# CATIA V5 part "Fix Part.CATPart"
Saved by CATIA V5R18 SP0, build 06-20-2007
Part number: Part4
Bounding box of the stored display mesh (mm): x -100 to 100, y -30 to 50, z -10 to 111
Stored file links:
  D:\shriniwas\v5_r19\c16_CAT_v5r19\c16_Part\Rack Joint\Fix Part.CATPart
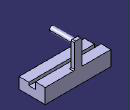
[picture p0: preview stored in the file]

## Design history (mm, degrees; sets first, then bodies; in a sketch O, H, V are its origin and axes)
Body1 (main body)
  Sketch1 on yz-plane, origin (0, 0, 0), H (0, 1, 0), V (0, 0, 1)
    line L1 (50, 35) -> (50, -10)
    line L2 (50, -10) -> (-30, -10)
    line L3 (0, 15) -> (20, 15)
    line L4 (20, 15) -> (20, 35)
    point P5 (0, 15)
    reference intersected line E1 through (0, 0) direction (-1, 0) from xy-plane
    reference intersected line E3 through (0, 0) direction (0, 1) from zx-plane
    line L5 (20, 35) -> (50, 35)
    reference intersected line E4 through (0, 0) direction (-1, 0) from xy-plane
    reference intersected line E6 through (0, 0) direction (0, 1) from zx-plane
    line L6 (0, 15) -> (0, 24)
    line L7 (0, 24) -> (-30, 24)
    line L8 (-30, 24) -> (-30, -10)
    distance H L2 = 10
    distance V L1 = 50
    distance E1 L3 = 15
    length L6 = 9
    length L4 = 20
    length L3 = 20
    length L2 = 80
    vertical: L1 V, L4 V, E3 V, E6 V, L6 V, L8 V
    horizontal: L2 H, L3 H, E1 H, L5 H, E4 H, L7 H
    perpendicularity: E1 L1
    coincidence: P5 V
  Pad1: profile Sketch1, direction (1, 0, 0), length 100, mirrored extent
  Sketch2 on face of Pad1 from Sketch1.L1, origin (0, 50, 0), H (-1, 0, 0), V (0, 0, 1)
    circle A1 centre (0, 100) radius 7.5
    point P1 (0, 100)
    radius A1 = 7.5
    distance H P1 = 100
    coincidence: P1 V
  Pad2: profile Sketch2, direction (0, -1, 0), up to face of Pad1 from Sketch1.L8
  Sketch3 on face of Pad1 from Sketch1.L1, origin (0, 50, 0), H (-1, 0, 0), V (0, 0, 1)
    line L1 (-11, 111) -> (11, 111)
    line L2 (11, 111) -> (11, -10)
    line L3 (11, -10) -> (-11, -10)
    line L4 (-11, -10) -> (-11, 111)
    length L3 = 22
    distance V L2 = 11
    distance L1 L3 = 121
    distance L3 H = 10
    horizontal: L1 H, L3 H
    vertical: L2 V, L4 V
  Pad3: profile Sketch3, direction (0, -1, 0), length 10
  Fillet1: radius 3, on edge [end face of Pad3 | face of Pad1 from Sketch1.L5]; edge [face of Pad3 from Sketch3.L4 | face of Pad1 from Sketch1.L5]; edge [face of Pad1 from Sketch1.L5 | face of Pad3 from Sketch3.L2]; edge [face of Pad2 from Sketch2.A1 | end face of Pad3]; edge [face of Pad3 from Sketch3.L1 | face of Pad3 from Sketch3.L4]; edge [face of Pad3 from Sketch3.L2 | face of Pad3 from Sketch3.L1]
